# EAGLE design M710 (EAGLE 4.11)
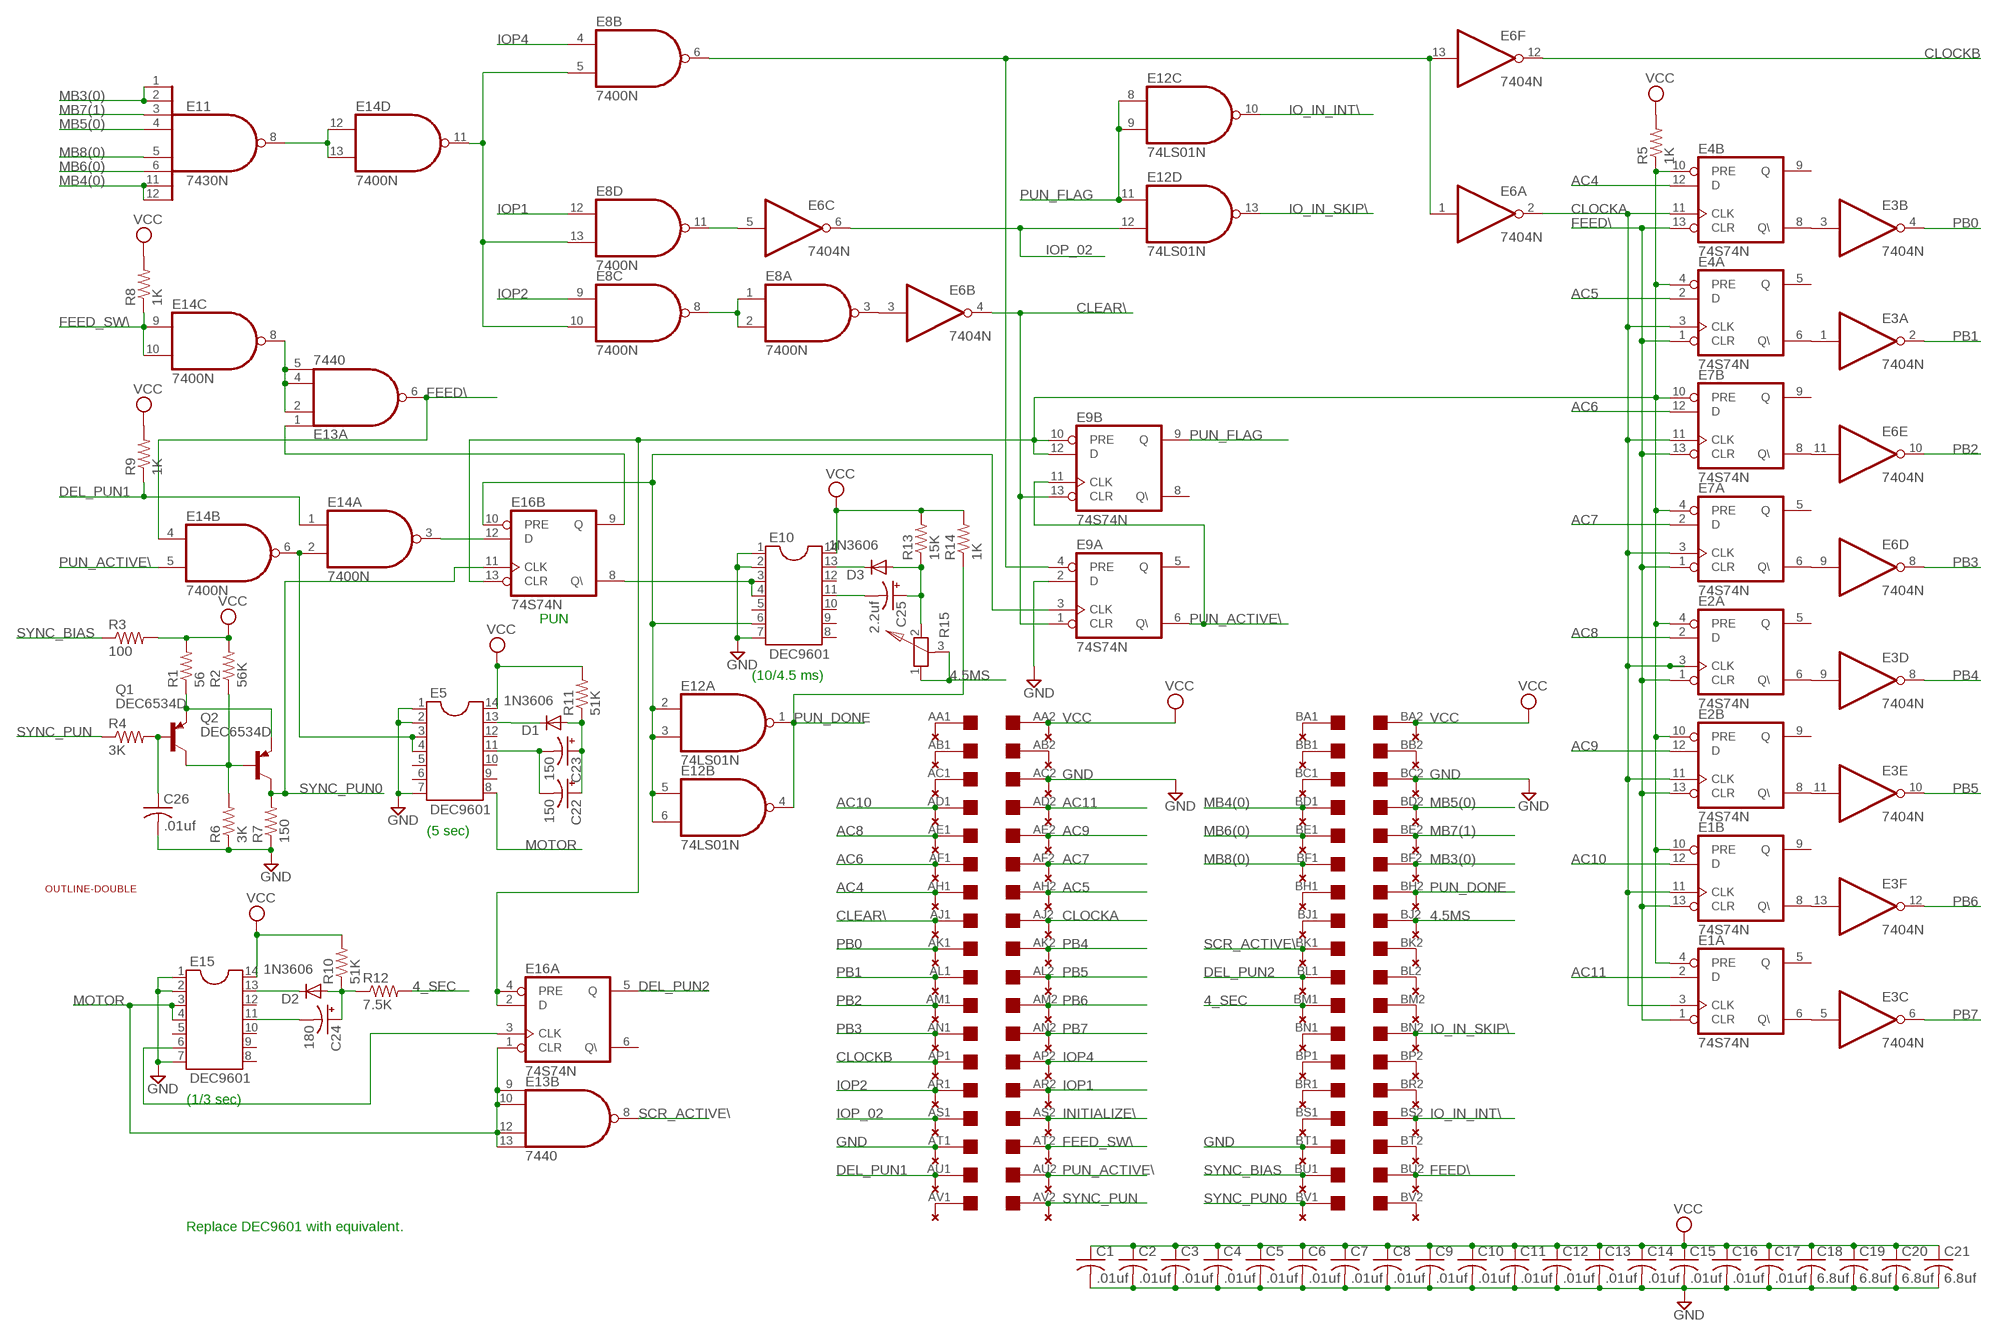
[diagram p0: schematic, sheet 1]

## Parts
C1  .01uf  C-US050-025X075  [C050-025X075]
C2  .01uf  C-US050-025X075  [C050-025X075]
C3  .01uf  C-US050-025X075  [C050-025X075]
C4  .01uf  C-US050-025X075  [C050-025X075]
C5  .01uf  C-US050-025X075  [C050-025X075]
C6  .01uf  C-US050-025X075  [C050-025X075]
C7  .01uf  C-US050-025X075  [C050-025X075]
C8  .01uf  C-US050-025X075  [C050-025X075]
C9  .01uf  C-US050-025X075  [C050-025X075]
C10  .01uf  C-US050-025X075  [C050-025X075]
C11  .01uf  C-US050-025X075  [C050-025X075]
C12  .01uf  C-US050-025X075  [C050-025X075]
C13  .01uf  C-US050-025X075  [C050-025X075]
C14  .01uf  C-US050-025X075  [C050-025X075]
C15  .01uf  C-US050-025X075  [C050-025X075]
C16  .01uf  C-US050-025X075  [C050-025X075]
C17  .01uf  C-US050-025X075  [C050-025X075]
C18  6.8uf  C-US150-054X183  [C150-054X183]
C19  6.8uf  C-US150-054X183  [C150-054X183]
C20  6.8uf  C-US150-054X183  [C150-054X183]
C21  6.8uf  C-US150-054X183  [C150-054X183]
C22  150  CPOL-USE5-8.5  [E5-8,5]
C23  150  CPOL-USE5-8.5  [E5-8,5]
C24  180  CPOL-USE5-8.5  [E5-8,5]
C25  2.2uf  CPOL-USE5-8.5  [E5-8,5]
C26  .01uf  C-US050-025X075  [C050-025X075]
D1  1N3606  1N4004  [DO41-10]
D2  1N3606  1N4004  [DO41-10]
D3  1N3606  1N4004  [DO41-10]
E1  74S74N  [DIL14]
E2  74S74N  [DIL14]
E3  7404N  [DIL14]
E4  74S74N  [DIL14]
E5  DEC9601  DIL14  [DIL14]
E6  7404N  [DIL14]
E7  74S74N  [DIL14]
E8  7400N  [DIL14]
E9  74S74N  [DIL14]
E10  DEC9601  DIL14  [DIL14]
E11  7430N  [DIL14]
E12  74LS01N  [DIL14]
E13  7440  74S20N  [DIL14]
E14  7400N  [DIL14]
E15  DEC9601  DIL14  [DIL14]
E16  74S74N  [DIL14]
Q1  DEC6534D  2N3906  [TO92]
Q2  DEC6534D  2N3906  [TO92]
R1  56  R-US_0207/7  [0207/7]
R2  56K  R-US_0207/7  [0207/7]
R3  100  R-US_0207/7  [0207/7]
R4  3K  R-US_0207/7  [0207/7]
R5  1K  R-US_0207/7  [0207/7]
R6  3K  R-US_0207/7  [0207/7]
R7  150  R-US_0207/7  [0207/7]
R8  1K  R-US_0207/7  [0207/7]
R9  1K  R-US_0207/7  [0207/7]
R10  51K  R-US_0207/7  [0207/7]
R11  51K  R-US_0207/7  [0207/7]
R12  7.5K  R-US_0207/7  [0207/7]
R13  15K  R-US_0207/7  [0207/7]
R14  1K  R-US_0207/7  [0207/7]
R15  POT-TRIM  [PT-SPIN]
U$1  OUTLINE-DOUBLE  [DOUBLE]
U$2  DOUBLE  [EDGE-CON4]
U$5  THRU-HOLE2  [THRU-HOLEB]
U$7  THRU-HOLE2  [THRU-HOLEB]

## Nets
4.5MS: R15.1 R15.3 U$2.BJ2 U$5.J2
4_SEC: R12.2 U$2.BM1 U$5.M1
AC4: E4.12(B:D) U$2.AH1 U$7.H1
AC5: E4.2(A:D) U$2.AH2 U$7.H2
AC6: E7.12(B:D) U$2.AF1 U$7.F1
AC7: E7.2(A:D) U$2.AF2 U$7.F2
AC8: E2.2(A:D) U$2.AE1 U$7.E1
AC9: E2.12(B:D) U$2.AE2 U$7.E2
AC10: E1.12(B:D) U$2.AD1 U$7.D1
AC11: E1.2(A:D) U$2.AD2 U$7.D2
CLEAR\: E6.4(B:O) E9.1(A:CLR) E9.13(B:CLR) U$2.AJ1 U$7.J1
CLOCKA: E1.3(A:CLK) E1.11(B:CLK) E2.3(A:CLK) E2.11(B:CLK) E4.3(A:CLK) E4.11(B:CLK) E6.2(A:O) E7.3(A:CLK) E7.11(B:CLK) U$2.AJ2 U$7.J2
CLOCKB: E6.12(F:O) U$2.AP1 U$7.P1
DEL_PUN1: E14.1(A:I0) R9.1 U$2.AU1 U$7.U1
DEL_PUN2: E16.5(A:Q) U$2.BL1 U$5.L1
FEED\: E1.1(A:CLR) E1.13(B:CLR) E2.1(A:CLR) E2.13(B:CLR) E4.1(A:CLR) E4.13(B:CLR) E7.1(A:CLR) E7.13(B:CLR) E13.6(A:O) E14.4(B:I0) U$2.BU2 U$5.U2
FEED_SW\: E14.9(C:I0) E14.10(C:I1) R8.1 U$2.AT2 U$7.T2
GND: C1.2 C2.2 C3.2 C4.2 C5.2 C6.2 C7.2 C8.2 C9.2 C10.2 C11.2 C12.2 C13.2 C14.2 C15.2 C16.2 C17.2 C18.2 C19.2 C20.2 C21.2 C26.2 E5.1 E5.2 E5.7 E9.2(A:D) E10.1 E10.2 E10.7 E15.1 E15.2 E15.7 R6.1 R7.1 U$2.AC2 U$2.AT1 U$2.BC2 U$2.BT1 U$5.C2 U$5.T1 U$7.C2 U$7.T1
INITIALIZE\: U$2.AS2 U$7.S2
IO_IN_INT\: E12.10(C:O) U$2.BS2 U$5.S2
IO_IN_SKIP\: E12.13(D:O) U$2.BN2 U$5.N2
IOP1: E8.12(D:I0) U$2.AR2 U$7.R2
IOP2: E8.9(C:I0) U$2.AR1 U$7.R1
IOP4: E8.4(B:I0) U$2.AP2 U$7.P2
IOP_02: E6.6(C:O) E12.12(D:I1) U$2.AS1 U$7.S1
MB3(0): E11.1(I0) E11.2(I1) U$2.BF2 U$5.F2
MB4(0): E11.11(I6) E11.12(I7) U$2.BD1 U$5.D1
MB5(0): E11.4(I3) U$2.BD2 U$5.D2
MB6(0): E11.6(I5) U$2.BE1 U$5.E1
MB7(1): E11.3(I2) U$2.BE2 U$5.E2
MB8(0): E11.5(I4) U$2.BF1 U$5.F1
MOTOR: E5.8 E13.9(B:I0) E13.10(B:I1) E13.12(B:I2) E13.13(B:I3) E15.3 E15.4 E16.1(A:CLR)
N$1: U$2.AB2 U$7.B2
N$2: E3.3(B:I) E4.8(B:Q\)
N$3: E3.1(A:I) E4.6(A:Q\)
N$4: E6.1(A:I) E6.13(F:I) E8.6(B:O) E9.4(A:PRE)
N$5: E11.8(O) E14.12(D:I0) E14.13(D:I1)
N$6: E6.3(B:I) E8.3(A:O)
N$7: E8.1(A:I0) E8.2(A:I1) E8.8(C:O)
N$8: E8.5(B:I1) E8.10(C:I1) E8.13(D:I1) E14.11(D:O)
N$9: E2.6(A:Q\) E3.9(D:I)
N$10: E2.8(B:Q\) E3.11(E:I)
N$11: E1.8(B:Q\) E3.13(F:I)
N$12: E1.6(A:Q\) E3.5(C:I)
N$13: E6.11(E:I) E7.8(B:Q\)
N$14: E6.9(D:I) E7.6(A:Q\)
N$15: U$2.AV1 U$7.V1
N$16: E6.5(C:I) E8.11(D:O)
N$17: U$2.AC1 U$7.C1
N$18: U$2.AB1 U$7.B1
N$19: Q1.1(C) Q2.2(B) R2.1 R6.2
N$20: U$2.BS1 U$5.S1
N$21: U$2.BR1 U$5.R1
N$22: U$2.BP1 U$5.P1
N$23: U$2.BN1 U$5.N1
N$26: U$2.AA1 U$7.A1
N$27: U$2.BJ1 U$5.J1
N$28: U$2.BH1 U$5.H1
N$29: U$2.BC1 U$5.C1
N$30: U$2.BB1 U$5.B1
N$31: U$2.BA1 U$5.A1
N$32: U$2.BV2 U$5.V2
N$33: U$2.BT2 U$5.T2
N$34: U$2.BR2 U$5.R2
N$35: U$2.BP2 U$5.P2
N$36: Q1.3(E) Q2.3(E) R1.1
N$37: U$2.BM2 U$5.M2
N$38: C26.1 Q1.2(B) R4.2
N$39: U$2.BL2 U$5.L2
N$40: C24.- E15.11
N$41: E13.2(A:I1) E13.4(A:I2) E13.5(A:I3) E14.8(C:O)
N$42: U$2.BK2 U$5.K2
N$43: U$2.BB2 U$5.B2
N$47: E1.4(A:PRE) E1.10(B:PRE) E2.4(A:PRE) E2.10(B:PRE) E4.4(A:PRE) E4.10(B:PRE) E7.4(A:PRE) E7.10(B:PRE) E9.10(B:PRE) E9.12(B:D) E16.2(A:D) E16.4(A:PRE) E16.13(B:CLR) R5.1
N$49: C25.- E10.11
N$53: E13.1(A:I0) E16.9(B:Q)
N$54: E14.3(A:O) E16.12(B:D)
N$55: E5.3 E5.4 E14.2(A:I1) E14.6(B:O)
N$56: C22.- C23.- E5.11
N$57: D1.C E5.13
N$58: C22.+ C23.+ D1.A R11.1
N$59: D2.C E15.13
N$60: C24.+ D2.A R10.1 R12.1
N$61: E15.6 E16.3(A:CLK)
N$63: D3.C E10.13
N$64: C25.+ D3.A R13.1 R15.2
N$65: E10.3 E10.4 E16.8(B:Q\)
N$66: E9.3(A:CLK) E10.6 E12.2(A:I0) E12.3(A:I1) E12.5(B:I0) E12.6(B:I1) E16.10(B:PRE)
PB0: E3.4(B:O) U$2.AK1 U$7.K1
PB1: E3.2(A:O) U$2.AL1 U$7.L1
PB2: E6.10(E:O) U$2.AM1 U$7.M1
PB3: E6.8(D:O) U$2.AN1 U$7.N1
PB4: E3.8(D:O) U$2.AK2 U$7.K2
PB5: E3.10(E:O) U$2.AL2 U$7.L2
PB6: E3.12(F:O) U$2.AM2 U$7.M2
PB7: E3.6(C:O) U$2.AN2 U$7.N2
PUN_ACTIVE\: E9.6(A:Q\) E9.11(B:CLK) E14.5(B:I1) U$2.AU2 U$7.U2
PUN_DONE: E12.1(A:O) E12.4(B:O) R14.1 U$2.BH2 U$5.H2
PUN_FLAG: E9.9(B:Q) E12.8(C:I0) E12.9(C:I1) E12.11(D:I0)
SCR_ACTIVE\: E13.8(B:O) U$2.BK1 U$5.K1
SYNC_BIAS: R3.1 U$2.BU1 U$5.U1
SYNC_PUN: R4.1 U$2.AV2 U$7.V2
SYNC_PUN0: E16.11(B:CLK) Q2.1(C) R7.2 U$2.BV1 U$5.V1
VCC: C1.1 C2.1 C3.1 C4.1 C5.1 C6.1 C7.1 C8.1 C9.1 C10.1 C11.1 C12.1 C13.1 C14.1 C15.1 C16.1 C17.1 C18.1 C19.1 C20.1 C21.1 E5.14 E10.14 E15.14 R1.2 R2.2 R3.2 R5.2 R8.2 R9.2 R10.2 R11.2 R13.2 R14.2 U$2.AA2 U$2.BA2 U$5.A2 U$7.A2
Unconnected: E1.5(A:Q) E1.9(B:Q) E2.5(A:Q) E2.9(B:Q) E4.5(A:Q) E4.9(B:Q) E5.5 E5.6 E5.9 E5.10 E5.12 E7.5(A:Q) E7.9(B:Q) E9.5(A:Q) E9.8(B:Q\) E10.5 E10.8 E10.9 E10.10 E10.12 E15.5 E15.8 E15.9 E15.10 E15.12 E16.6(A:Q\)

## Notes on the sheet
- PUN
- (10/4.5 ms)
- (5 sec)
- (1/3 sec)
- Replace DEC9601 with equivalent.

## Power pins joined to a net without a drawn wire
GND: E1.7(P:GND) E2.7(P:GND) E3.7(P:GND) E4.7(P:GND) E6.7(P:GND) E7.7(P:GND) E8.7(P:GND) E9.7(P:GND) E11.7(GND) E12.7(P:GND) E13.7(P:GND) E14.7(P:GND) E16.7(P:GND)
VCC: E1.14(P:VCC) E2.14(P:VCC) E3.14(P:VCC) E4.14(P:VCC) E6.14(P:VCC) E7.14(P:VCC) E8.14(P:VCC) E9.14(P:VCC) E11.14(VCC) E12.14(P:VCC) E13.14(P:VCC) E14.14(P:VCC) E16.14(P:VCC)

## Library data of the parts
C1-C21 C26 = rcl:C-US: CAPACITOR, American symbol
C22-C25 = rcl:CPOL-US: POLARIZED CAPACITOR, American symbol
D1-D3 = diode:1N4004: DIODE
E1 E2 E4 E7 E9 E16 = 74xx-us:74*74: Dual D type positive edge triggered FLIP FLOP, preset and clear
E3 E6 = 74xx-us:74*04: Hex INVERTER
E5 E10 E15 = ic-package:DIL14: Dual In Line
E8 E14 = 74xx-us:74*00: Quad 2-input NAND gate
E11 = 74xx-us:74*30: 8-input NAND gate
E12 = 74xx-us:74*01: Quad 2-input NAND gate, open collector
E13 = 74xx-us:74*20: Dual 4-input NAND gate
Q1 Q2 = transistor-pnp:2N3906: PNP Transistor
R1-R14 = rcl:R-US_: RESISTOR, American symbol
R15 = discrete:POT-TRIM
U$1 = dec-con:OUTLINE-*: Board outlines for DEC boards.
U$2 = dec-con:DOUBLE: Double-Height DEC board
U$5 U$7 = dec-con:THRU-HOLE2: Thru-Hole addition to double-sided edge connector.

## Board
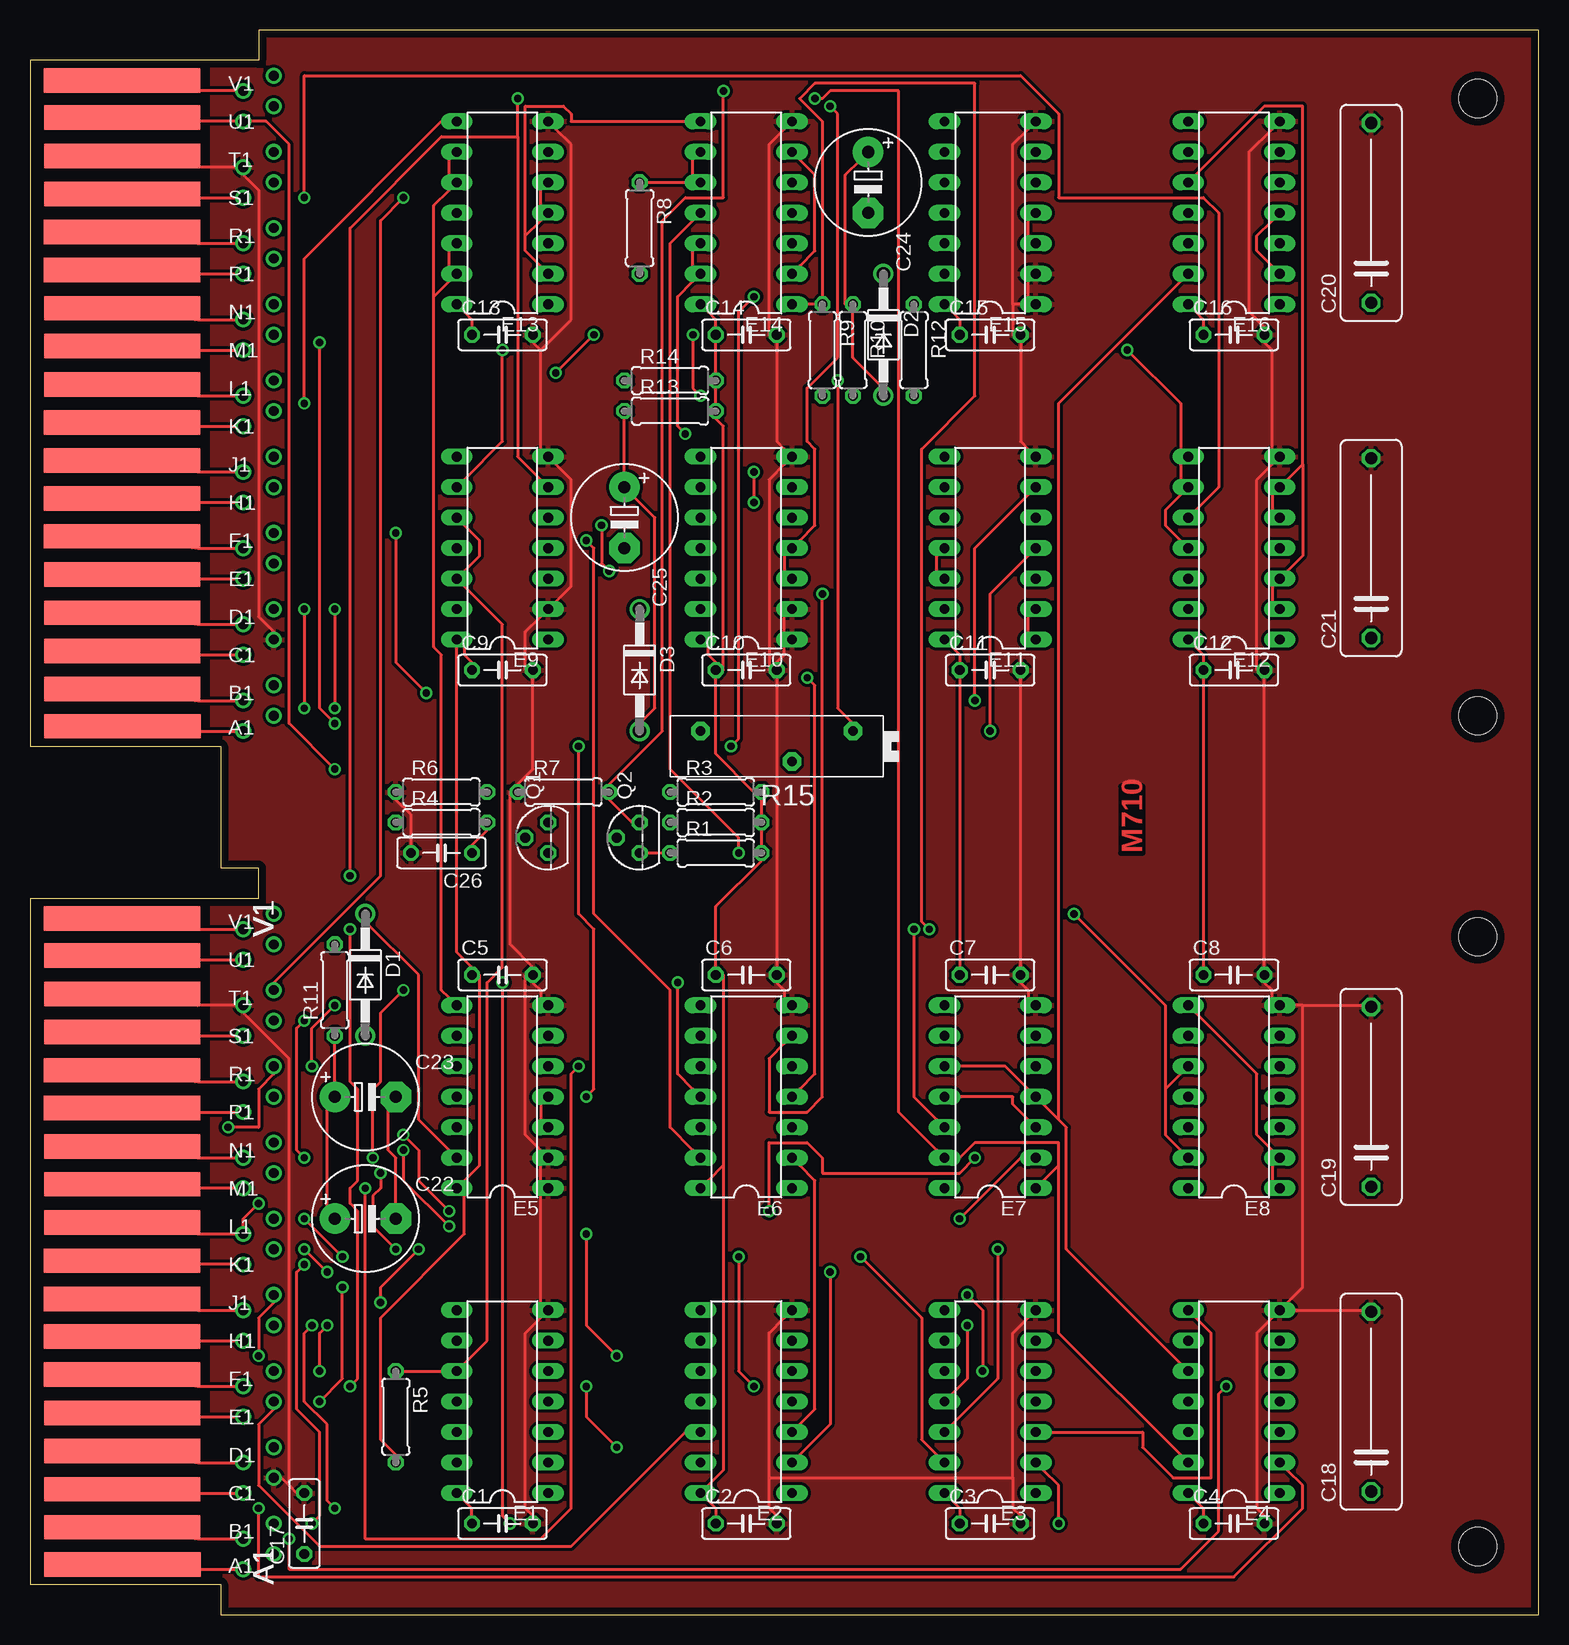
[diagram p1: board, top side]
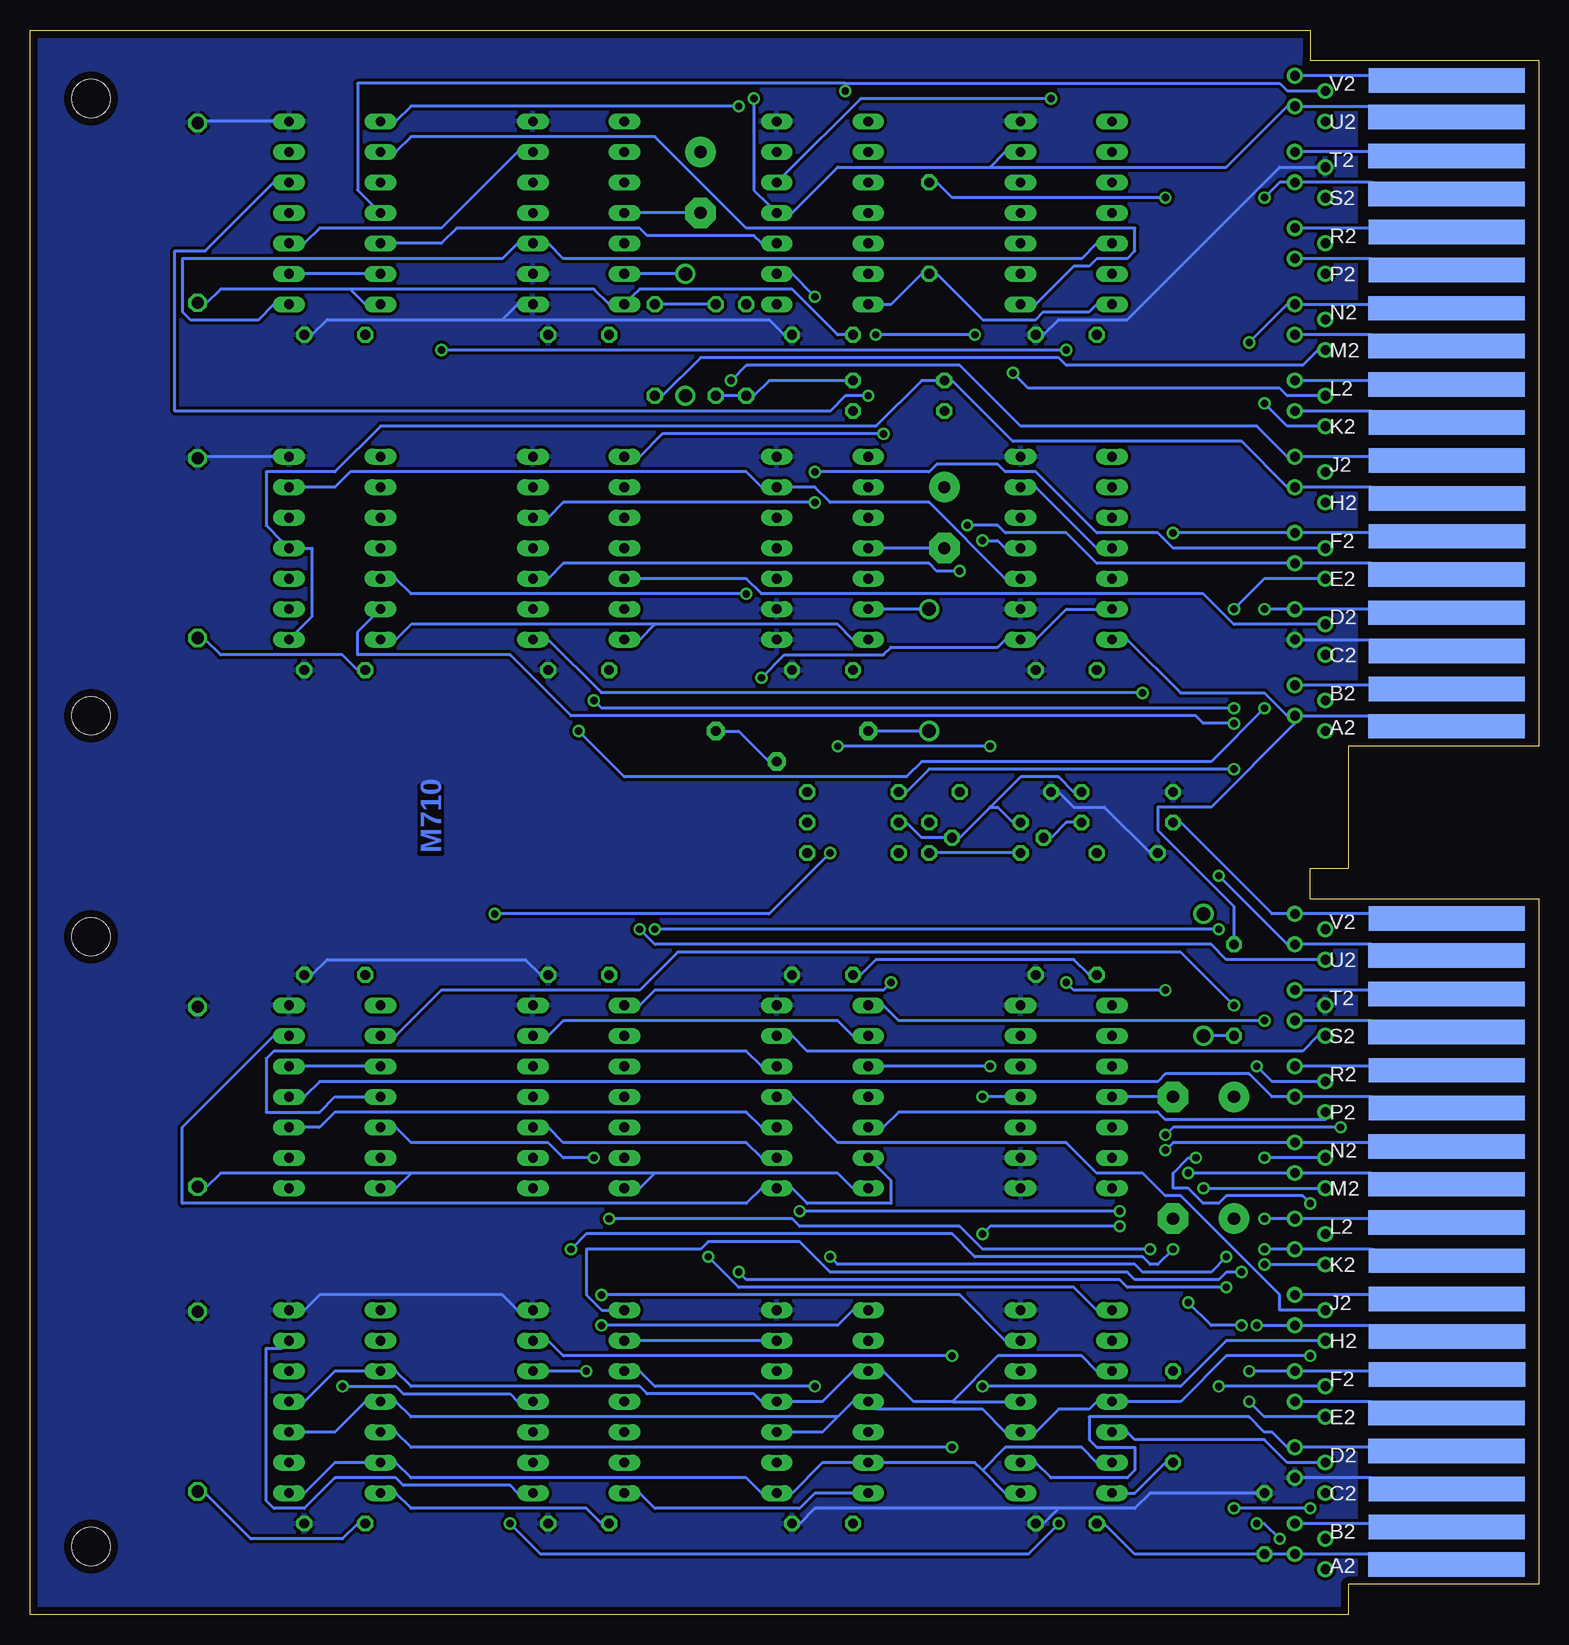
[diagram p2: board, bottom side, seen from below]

Size 125.73 x 132.08 mm. Coordinates in mm from the lower left corner, seen from the top.
Outline: 0,129.03 0,72.39
Copper layers (1*16): Top 0.035mm / dielectric 1.5mm / Bottom 0.035mm
Design rules "olimex10mil": minimum track width 10mil, minimum drill 24mil, track to track 10mil, track to pad 10mil, pad to pad 10mil, via to via 10mil, smd to smd 10mil, copper to edge 25mil, drill to drill 10mil, minimum pad ring 10mil, minimum via ring 8mil, stop-mask expansion 0mil, vias tented up to drill 0mil, thermal gap 10mil
vRestrict: area 31.8,108 to 41.9,125.7; area 49.5,108 to 59.7,125.7; area 67.3,108 to 77.5,125.7; area 85.1,108 to 95.3,125.7; area 102.9,108 to 113,125.7; area 31.8,80 to 41.9,97.8; area 49.5,80 to 59.7,97.8; area 67.3,80 to 77.5,97.8; area 85.1,80 to 95.3,97.8; area 31.8,34.3 to 41.9,52.1; area 49.5,34.3 to 59.7,52.1; area 67.3,34.3 to 77.5,52.1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

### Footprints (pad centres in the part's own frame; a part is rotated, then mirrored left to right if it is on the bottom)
C050-025X075 = drill 0.813 octagon: 1 -2.54,0; 2 2.54,0
C150-054X183 = drill 1.016 octagon: 1 -7.493,0; 2 7.493,0
E5-8,5 = drill 1.016 pad 2.54 round: + -2.54,0 | drill 1.016 pad 2.54 octagon: - 2.54,0
DO41-10 = drill 1.118 round: A 5.08,0; C -5.08,0
DIL14 = drill 0.813 long: 1 -7.62,-3.81; 2 -5.08,-3.81; 3 -2.54,-3.81; 4 0,-3.81; 5 2.54,-3.81; 6 5.08,-3.81; 7 7.62,-3.81; 8 7.62,3.81; 9 5.08,3.81; 10 2.54,3.81; 11 0,3.81; 12 -2.54,3.81; 13 -5.08,3.81; 14 -7.62,3.81
TO92 = drill 0.813 octagon: 1 1.27,0; 2 0,1.905; 3 -1.27,0
0207/7 = drill 0.813 octagon: 1 -3.81,0; 2 3.81,0
PT-SPIN = drill 0.813 pad 1.524 octagon: 1 -6.35,-1.27; 2 6.35,-1.27; 3 -1.27,1.27
DOUBLE = hole 3.175: 120.65,56.515; 120.65,5.715; 120.65,74.93; 120.65,126.365
EDGE-CON4 = smd 13.017 x 2.032: AA1 7.709,4.207; AB1 7.684,7.312; AC1 7.684,10.474; AD1 7.684,13.665; AE1 7.693,16.84; AF1 7.668,20.041; AH1 7.668,23.19; AJ1 7.668,26.34; AK1 7.668,29.515; AL1 7.693,32.69; AM1 7.693,35.89; AN1 7.693,39.04; AP1 7.668,42.24; AR1 7.668,45.39; AS1 7.693,48.565; AT1 7.693,51.74; AU1 7.693,54.94; AV1 7.668,58.026; BA1 7.709,74.057; BB1 7.684,77.162; BC1 7.684,80.324; BD1 7.684,83.515; BE1 7.693,86.69; BF1 7.668,89.891; BH1 7.668,93.04; BJ1 7.668,96.19; BK1 7.668,99.365; BL1 7.693,102.54; BM1 7.693,105.74; BN1 7.693,108.89; BP1 7.668,112.09; BR1 7.668,115.24; BS1 7.693,118.415; BT1 7.693,121.59; BU1 7.693,124.79; BV1 7.668,127.876 | smd 13.017 x 2.032 bottom: AA2 7.69,4.207; AB2 7.668,7.328; AC2 7.668,10.49; AD2 7.693,13.665; AE2 7.693,16.84; AF2 7.642,20.041; AH2 7.642,23.19; AJ2 7.668,26.34; AK2 7.668,29.515; AL2 7.693,32.69; AM2 7.693,35.89; AN2 7.693,39.04; AP2 7.668,42.24; AR2 7.668,45.39; AS2 7.693,48.565; AT2 7.693,51.74; AU2 7.693,54.966; AV2 7.668,58.026; BA2 7.69,74.057; BB2 7.668,77.178; BC2 7.668,80.34; BD2 7.693,83.515; BE2 7.693,86.69; BF2 7.642,89.891; BH2 7.642,93.04; BJ2 7.668,96.19; BK2 7.668,99.365; BL2 7.693,102.54; BM2 7.693,105.74; BN2 7.693,108.89; BP2 7.668,112.09; BR2 7.668,115.24; BS2 7.693,118.415; BT2 7.693,121.59; BU2 7.693,124.816; BV2 7.668,127.876
THRU-HOLEB = drill 0.813 pad 1.27 round: A1 17.78,3.81; A2 20.32,5.08; B1 17.78,6.35; B2 20.32,7.62; C1 17.78,10.16; C2 20.32,11.43; D1 17.78,12.7; D2 20.32,13.97; E1 17.78,16.51; E2 20.32,17.78; F1 17.78,19.05; F2 20.32,20.32; H1 17.78,22.86; H2 20.32,24.13; J1 17.78,25.4; J2 20.32,26.67; K1 17.78,29.21; K2 20.32,30.48; L1 17.78,31.75; L2 20.32,33.02; M1 17.78,35.56; M2 20.32,36.83; N1 17.78,38.1; N2 20.32,39.37; P1 17.78,41.91; P2 20.32,43.18; R1 17.78,44.45; R2 20.32,45.72; S1 17.78,48.26; S2 20.32,49.53; T1 17.78,50.8; T2 20.32,52.07; U1 17.78,54.61; U2 20.32,55.88; V1 17.78,57.15; V2 20.32,58.42

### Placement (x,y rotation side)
C1  39.37,7.62 0 top
C2  59.69,7.62 0 top
C3  80.01,7.62 0 top
C4  100.33,7.62 0 top
C5  39.37,53.34 0 top
C6  59.69,53.34 0 top
C7  80.01,53.34 0 top
C8  100.33,53.34 0 top
C9  39.37,78.74 0 top
C10  59.69,78.74 0 top
C11  80.01,78.74 0 top
C12  100.33,78.74 0 top
C13  39.37,106.68 0 top
C14  59.69,106.68 0 top
C15  80.01,106.68 0 top
C16  100.33,106.68 0 top
C17  22.86,7.62 90 top
C18  111.76,17.78 90 top
C19  111.76,43.18 90 top
C20  111.76,116.84 90 top
C21  111.76,88.9 90 top
C22  27.94,33.02 0 top
C23  27.94,43.18 0 top
C24  69.85,119.38 270 top
C25  49.53,91.44 270 top
C26  34.29,63.5 180 top
D1  27.94,53.34 270 top
D2  71.12,106.68 270 top
D3  50.8,78.74 270 top
E1  39.37,17.78 90 top
E2  59.69,17.78 90 top
E3  80.01,17.78 90 top
E4  100.33,17.78 90 top
E5  39.37,43.18 90 top
E6  59.69,43.18 90 top
E7  80.01,43.18 90 top
E8  100.33,43.18 90 top
E9  39.37,88.9 90 top
E10  59.69,88.9 90 top
E11  80.01,88.9 90 top
E12  100.33,88.9 90 top
E13  39.37,116.84 90 top
E14  59.69,116.84 90 top
E15  80.01,116.84 90 top
E16  100.33,116.84 90 top
Q1  43.18,64.77 90 top
Q2  50.8,64.77 90 top
R1  57.15,63.5 0 top
R2  57.15,66.04 0 top
R3  57.15,68.58 0 top
R4  34.29,66.04 0 top
R5  30.48,16.51 270 top
R6  34.29,68.58 0 top
R7  44.45,68.58 0 top
R8  50.8,115.57 270 top
R9  66.04,105.41 270 top
R10  68.58,105.41 270 top
R11  25.4,52.07 90 top
R12  73.66,105.41 270 top
R13  53.34,100.33 0 top
R14  53.34,102.87 0 top
R15  62.23,72.39 180 top
U$1  0,0 0 top
U$2  0,0 0 top
U$5  0,69.85 0 top
U$7  0,0 0 top

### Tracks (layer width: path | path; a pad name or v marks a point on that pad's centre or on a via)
4.5MS  (via drill 0.61)
  Top 0.254: v67.31,102.87 67.31,75.56 68.58,74.3 R15.1
  Bottom 0.254: R15.3 64.14,71.12 66.68,73.66 67.95,73.66 R15.1 | v67.31,102.87 66.04,104.14 48.26,104.14 43.18,99.06 23.5,99.06 20.96,96.52 U$5.J2 19.69,96.52 13.97,96.52 U$2.BJ2
4_SEC
  Top 0.254: U$5.M1 17.15,105.41 13.97,105.41 U$2.BM1
  Bottom 0.254: R12.2 73.03,101.6 69.85,104.78 40.01,104.78 39.37,104.14 19.69,104.14 18.42,105.41 U$5.M1
AC4  (via drill 0.61)
  Top 0.254: U$7.H1 17.15,22.86 13.97,22.86 U$2.AH1 | v48.9,13.97 46.36,16.51 v46.36,19.05
  Bottom 0.254: v48.9,13.97 93.98,13.97 95.25,15.24 E4.12 | v46.36,19.05 29.85,19.05 26.04,22.86 18.42,22.86 U$7.H1
AC5  (via drill 0.61)
  Top 0.254: v19.05,8.89 19.05,3.17 100.33,3.17 106.05,8.89 106.05,10.79 104.78,12.06 E4.2 | v25.4,8.89 24.77,9.53 24.77,15.88 22.86,17.78 22.86,23.5 v23.5,24.13
  Bottom 0.254: v19.05,8.89 v25.4,8.89 | v23.5,24.13 20.96,24.13 U$7.H2 19.69,24.13 13.97,24.13 U$2.AH2
AC6  (via drill 0.61)
  Top 0.254: U$7.F1 17.15,19.05 13.97,19.05 U$2.AF1 | v73.66,57.15 73.66,43.18 75.57,41.27 E7.12 | v26.67,57.15 26.67,44.45 27.31,43.81 27.31,36.2 26.67,35.56 26.67,34.29 27.31,33.66 27.31,19.68 v26.67,19.05
  Bottom 0.254: v26.67,57.15 v73.66,57.15 | v26.67,19.05 18.42,19.05 U$7.F1
AC7  (via drill 0.61)
  Top 0.254: v77.47,33.02 82.55,38.1 E7.2 | v32.39,30.48 29.21,27.3 v29.21,26.04 | v24.77,24.13 24.13,23.5 v24.13,20.32
  Bottom 0.254: v77.47,33.02 62.23,33.02 61.6,32.38 48.26,32.38 46.36,30.48 v32.39,30.48 | v29.21,26.04 27.31,24.13 v24.77,24.13 | v24.13,20.32 20.96,20.32 U$7.F2 19.69,20.32 13.97,20.32 U$2.AF2
AC8  (via drill 0.61)
  Top 0.254: U$7.E1 17.15,16.51 13.97,16.51 U$2.AE1 | v66.68,28.57 66.68,15.88 64.14,13.34 E2.2 | v26.04,27.3 26.04,19.68 v24.13,17.78
  Bottom 0.254: v66.68,28.57 66.04,27.94 34.93,27.94 34.29,27.3 v26.04,27.3 | v24.13,17.78 22.86,16.51 18.42,16.51 U$7.E1
AC9
  Top 0.254: E2.12 54.61,15.24 45.09,5.71 24.13,5.71 19.05,10.79 19.05,15.88 20.32,17.14 U$7.E2
  Bottom 0.254: U$7.E2 19.69,17.78 13.97,17.78 U$2.AE2
AC10
  Top 0.254: U$7.D1 17.15,12.7 13.97,12.7 U$2.AD1
  Bottom 0.254: E1.12 34.29,15.24 33.66,14.61 22.86,14.61 20.96,12.7 18.42,12.7 U$7.D1
AC11
  Bottom 0.254: E1.2 41.91,12.7 40.64,11.43 34.29,11.43 33.66,12.06 33.66,13.97 36.83,13.97 37.47,14.61 37.47,16.51 24.13,16.51 22.86,15.24 22.23,15.24 20.96,13.97 U$7.D2 19.69,13.97 13.97,13.97 U$2.AD2
CLEAR\  (via drill 0.61)
  Top 0.254: U$7.J1 17.15,25.4 13.97,25.4 U$2.AJ1 | v64.77,78.11 65.41,77.47 65.41,45.09 64.14,43.81 E6.4
  Bottom 0.254: E9.13 36.83,83.82 39.37,83.82 41.91,81.28 E9.1 44.45,81.28 45.09,80.64 53.98,80.64 54.61,80.01 62.87,80.01 v64.77,78.11 | E6.4 62.23,43.18 58.42,39.37 39.37,39.37 36.83,36.83 33.02,36.83 31.12,34.92 29.85,34.92 21.59,26.67 21.59,25.4 18.42,25.4 U$7.J1
CLOCKA  (via drill 0.61)
  Top 0.254: E7.11 77.47,43.18 81.92,43.18 81.92,42.55 83.19,41.27 E7.3 | E6.2 64.14,37.47 65.41,36.2 65.41,17.14 64.14,15.88 E2.3 | v19.05,21.59 19.05,24.77 20.32,26.04 U$7.J2
  Bottom 0.254: U$7.J2 19.69,26.67 13.97,26.67 U$2.AJ2 | E6.2 64.77,38.1 66.04,39.37 81.28,39.37 82.55,40.64 E7.3 | E4.3 102.87,15.24 100.33,15.24 97.79,17.78 E4.11 95.25,17.78 93.98,16.51 58.42,16.51 | 58.42,16.51 59.69,15.24 62.23,15.24 E2.3 | 58.42,16.51 57.15,17.78 E2.11 55.25,17.14 46.36,17.14 44.45,15.24 E1.3 41.91,15.24 40.01,17.14 37.47,17.14 36.83,17.78 E1.11 34.29,17.78 29.85,17.78 26.04,21.59 v19.05,21.59
CLOCKB
  Top 0.254: U$7.P1 17.15,41.91 13.97,41.91 U$2.AP1
  Bottom 0.254: E6.12 54.61,40.64 53.34,41.91 31.75,41.91 31.12,41.27 17.78,41.27 U$7.P1
DEL_PUN1  (via drill 0.61)
  Top 0.254: E14.1 64.77,109.22 65.41,109.22 R9.1 66.04,109.86 66.04,124.46 64.14,126.36 65.41,127.64 78.74,127.64 78.74,101.6 74.3,97.16 74.3,57.78 v74.93,57.15 | U$7.U1 17.15,54.61 13.97,54.61 U$2.AU1
  Bottom 0.254: v74.93,57.15 73.66,55.88 27.31,55.88 26.04,54.61 18.42,54.61 U$7.U1
DEL_PUN2  (via drill 0.61)
  Top 0.254: U$5.L1 17.15,101.6 13.97,101.6 U$2.BL1 | v55.88,101.6 55.25,102.23 v55.25,106.68 | v43.82,103.5 v46.99,106.68
  Bottom 0.254: v55.88,101.6 57.79,101.6 59.06,100.33 113.67,100.33 113.67,113.67 111.13,113.67 105.41,119.38 E16.5 | v46.99,106.68 v55.25,106.68 | v43.82,103.5 42.55,102.23 21.59,102.23 20.96,101.6 18.42,101.6 U$5.L1
FEED\  (via drill 0.61)
  Top 0.254: 85.73,37.47 85.73,39.37 78.74,39.37 77.47,38.1 E7.13 75.57,38.73 72.39,41.91 72.39,127 66.68,127 66.04,126.36 v65.41,126.36 | 85.73,37.47 84.46,36.2 E7.1 | 85.73,37.47 85.73,23.5 95.89,13.34 E4.13
  Bottom 0.254: 45.72,120.65 44.45,121.92 E13.6 | 45.72,120.65 58.42,120.65 62.23,116.84 E14.4 64.14,117.47 65.41,118.75 v65.41,126.36 | 46.36,12.06 46.99,12.7 54.61,12.7 E2.13 57.15,12.7 59.69,12.7 62.23,10.16 E2.1 64.77,10.16 66.04,11.43 93.98,11.43 95.25,12.7 E4.13 97.79,12.7 100.33,12.7 102.87,10.16 E4.1 | 46.36,12.06 44.45,10.16 E1.1 | 46.36,12.06 44.45,13.97 38.1,13.97 36.83,12.7 E1.13 | U$2.BU2 13.97,125.73 19.69,125.73 U$5.U2 20.96,125.73 26.04,120.65 45.72,120.65
FEED_SW\  (via drill 0.61)
  Top 0.254: R8.1 51.44,119.38 54.61,119.38 E14.10 55.25,120.02 55.25,121.28 E14.9 | v31.12,118.11 29.21,116.2 29.21,61.59 20.32,52.7 U$7.T2
  Bottom 0.254: U$7.T2 19.69,52.07 13.97,52.07 U$2.AT2 | v31.12,118.11 48.9,118.11 50.17,119.38 R8.1
GND
  Top 0.254: E14.7 62.87,123.83 61.6,122.56 61.6,106.68 C14.2 62.23,106.05 62.23,97.79 62.87,97.16 E10.7 62.87,95.89 61.6,94.61 61.6,78.74 C10.2 | E6.7 62.87,51.44 62.87,52.07 62.23,52.7 C6.2 62.23,53.98 62.23,78.11 C10.2 | C10.2 62.23,79.38 62.87,80.01 62.87,80.64 E10.1 62.87,81.92 62.87,83.19 E10.2 | E15.2 83.19,111.12 83.19,109.86 E15.1 82.55,109.22 81.92,109.22 | E11.7 83.19,97.16 82.55,97.79 82.55,106.05 C15.2 81.92,106.68 81.92,109.22 | 81.92,109.22 81.92,122.56 83.19,123.83 E15.7 | E16.7 103.51,123.83 101.6,121.92 101.6,108.58 102.87,107.31 C16.2 102.87,106.05 103.51,105.41 103.51,97.16 E12.7 103.51,95.89 102.24,94.61 102.24,78.74 C12.2 102.87,78.11 102.87,53.98 C8.2 102.87,52.7 103.51,52.07 103.51,51.44 E8.7 105.41,50.8 106.05,50.8 | 61.6,11.43 61.6,23.5 62.87,24.77 E2.7 | 61.6,11.43 61.6,8.89 62.23,8.26 C2.2 | 81.92,11.43 81.92,23.5 83.19,24.77 E3.7 | 81.92,11.43 81.92,8.89 82.55,8.26 C3.2 | 61.6,11.43 81.92,11.43 | E7.7 83.19,51.44 83.19,52.07 82.55,52.7 C7.2 82.55,53.98 82.55,78.11 C11.2 | C4.2 102.87,8.26 102.24,8.89 102.24,23.5 103.51,24.77 E4.7 | C18.2 111.13,25.4 105.41,25.4 E4.7 | 106.05,50.8 111.13,50.8 C19.2 | 106.05,50.8 106.05,27.3 104.78,26.04 E4.7 | 21.59,10.79 20.96,11.43 U$7.C2 | 21.59,10.79 22.23,10.16 C17.2 | 21.59,10.79 21.59,46.35 17.78,50.16 U$7.T1 17.15,50.8 13.97,50.8 U$2.AT1 | C1.2 41.91,8.26 41.28,8.89 41.28,23.5 42.55,24.77 E1.7 42.55,26.04 42.55,34.92 E5.1 42.55,36.2 42.55,37.47 E5.2 42.55,38.73 41.28,40.01 41.28,53.34 C5.2 | 42.55,105.41 41.91,106.05 C13.2 | 42.55,105.41 42.55,97.16 E9.7 43.82,95.89 45.09,94.61 45.09,85.72 43.82,84.45 E9.2 42.55,83.19 41.28,81.92 41.28,78.74 C9.2 41.91,78.11 41.91,70.48 40.64,69.22 R7.1 40.01,68.58 40.01,55.88 41.91,53.98 C5.2
  Top 0.254: 42.55,105.41 45.09,107.95 45.09,122.56 43.82,123.83 E13.7 | C26.2 31.75,64.14 31.75,66.67 30.48,67.94 R6.1 | C5.2 41.91,52.7 42.55,52.07 42.55,51.44 E5.7 | U$5.C2 20.32,81.92 19.05,83.19 19.05,118.75 17.78,120.02 U$5.T1 17.15,120.65 13.97,120.65 U$2.BT1
  Bottom 0.254: E16.7 105.41,124.46 111.13,124.46 C20.2 | E12.7 105.41,96.52 111.13,96.52 C21.2 | 86.36,107.95 85.09,109.22 E15.1 | 86.36,107.95 100.97,107.95 102.24,106.68 C16.2 | C7.2 83.19,53.34 84.46,54.61 100.97,54.61 102.24,53.34 C8.2 | E3.7 85.09,25.4 86.36,26.67 101.6,26.67 102.87,25.4 E4.7 | 86.36,107.95 64.14,107.95 62.87,106.68 C14.2 | U$7.C2 19.69,11.43 13.97,11.43 U$2.AC2 | U$5.C2 19.69,81.28 13.97,81.28 U$2.BC2 | C26.2 32.39,63.5 36.2,67.31 38.74,67.31 40.01,68.58 R7.1 | U$5.T1 18.42,120.65 21.59,120.65 34.29,107.95 40.01,107.95 41.28,106.68 C13.2 | 40.01,8.89 33.66,8.89 32.39,10.16 23.5,10.16 C17.2 | 40.01,8.89 41.28,7.62 C1.2 | 40.01,8.89 60.33,8.89 61.6,7.62 C2.2
  pour Bottom (isolate 0.254): 125.73,132.08 125.73,0 15.24,0 15.24,132.08
  pour Top (isolate 0.254): 15.24,132.08 125.73,132.08 125.73,0 15.24,0
INITIALIZE\
  Bottom 0.254: U$7.S2 19.69,49.53 13.97,49.53 U$2.AS2
IO_IN_INT\  (via drill 0.61)
  Top 0.254: v22.86,118.11 22.86,128.27 82.55,128.27 85.73,125.09 85.73,118.11 97.79,118.11 99.06,116.84 99.06,93.98 97.16,92.08 E12.10
  Bottom 0.254: U$2.BS2 13.97,119.38 19.69,119.38 U$5.S2 20.96,119.38 21.59,119.38 v22.86,118.11
IO_IN_SKIP\  (via drill 0.61)
  Top 0.254: v25.4,74.3 24.13,75.56 v24.13,106.05
  Bottom 0.254: v25.4,74.3 27.94,74.3 28.58,74.93 80.65,74.93 85.73,80.01 98.43,80.01 98.43,81.92 97.16,83.19 E12.13 | v24.13,106.05 20.96,109.22 U$5.N2 19.69,109.22 13.97,109.22 U$2.BN2
IOP1  (via drill 0.61)
  Top 0.254: v78.74,38.1 77.47,36.83 66.04,36.83 66.04,38.1 64.77,39.37 61.6,39.37 v61.6,33.66 | v34.93,33.66 32.39,36.2 32.39,38.73 v31.12,40.01 | v16.51,40.64 19.05,40.64 19.05,43.81 20.32,45.09 U$7.R2
  Bottom 0.254: U$7.R2 19.69,45.72 13.97,45.72 U$2.AR2 | v78.74,38.1 81.28,38.1 82.55,39.37 93.98,39.37 95.25,40.64 E8.12 | v34.93,33.66 v61.6,33.66 | v31.12,40.01 30.48,40.64 v16.51,40.64
IOP2  (via drill 0.61)
  Top 0.254: U$7.R1 17.15,44.45 13.97,44.45 U$2.AR1 | v25.4,50.8 23.5,48.9 v23.5,45.72
  Bottom 0.254: v25.4,50.8 29.85,55.24 71.76,55.24 74.93,52.07 91.44,52.07 95.25,48.26 E8.9 | v23.5,45.72 22.23,44.45 18.42,44.45 U$7.R1
IOP4
  Bottom 0.254: E8.4 102.87,43.18 101.6,44.45 31.75,44.45 31.12,45.09 24.13,45.09 22.23,43.18 20.96,43.18 U$7.P2 19.69,43.18 13.97,43.18 U$2.AP2
IOP_02  (via drill 0.61)
  Top 0.254: U$7.S1 17.15,48.26 13.97,48.26 U$2.AS1 | v66.04,85.09 66.04,43.18 64.77,41.91 61.6,41.91 61.6,46.35 62.87,47.62 E6.6
  Bottom 0.254: E6.6 62.23,48.26 60.96,46.99 19.69,46.99 18.42,48.26 U$7.S1 | v66.04,85.09 93.98,85.09 95.25,86.36 E12.12
MB3(0)  (via drill 0.61)
  Top 0.254: E11.1 83.19,81.92 83.19,83.19 E11.2 | v33.02,76.83 30.48,79.38 v30.48,90.17
  Bottom 0.254: v33.02,76.83 78.11,76.83 82.55,81.28 E11.1 | v30.48,90.17 20.96,90.17 U$5.F2 19.69,90.17 13.97,90.17 U$2.BF2
MB4(0)
  Top 0.254: E11.12 75.57,87 75.57,88.27 E11.11 | U$5.D1 17.15,82.55 13.97,82.55 U$2.BD1
  Bottom 0.254: E11.12 74.93,86.36 66.04,86.36 64.77,85.09 27.94,85.09 25.4,82.55 18.42,82.55 U$5.D1
MB5(0)  (via drill 0.61)
  Top 0.254: v80.01,73.66 80.01,85.09 83.19,88.27 E11.4 | v22.86,83.82 v22.86,75.56
  Bottom 0.254: v80.01,73.66 76.2,69.85 52.71,69.85 51.44,71.12 27.31,71.12 v22.86,75.56 | v22.86,83.82 20.96,83.82 U$5.D2 19.69,83.82 13.97,83.82 U$2.BD2
MB6(0)  (via drill 0.61)
  Top 0.254: U$5.E1 17.15,86.36 13.97,86.36 U$2.BE1 | v78.74,76.2 78.74,88.9 83.19,93.34 E11.6 | v25.4,83.82 v25.4,75.56
  Bottom 0.254: v78.74,76.2 78.11,75.56 v25.4,75.56 | v25.4,83.82 22.86,86.36 18.42,86.36 U$5.E1
MB7(1)  (via drill 0.61)
  Top 0.254: v48.26,87 47.63,87.63 v47.63,90.81
  Bottom 0.254: v48.26,87 50.17,87 50.8,87.63 81.28,87.63 82.55,86.36 E11.3 | v47.63,90.81 45.09,90.81 44.45,90.17 39.37,90.17 36.83,87.63 20.96,87.63 U$5.E2 19.69,87.63 13.97,87.63 U$2.BE2
MB8(0)  (via drill 0.61)
  Top 0.254: U$5.F1 17.15,88.9 13.97,88.9 U$2.BF1 | v60.33,95.25 v60.33,92.71
  Bottom 0.254: v60.33,92.71 81.28,92.71 82.55,91.44 E11.5 | v60.33,95.25 50.8,95.25 50.17,95.89 45.09,95.89 44.45,95.25 41.91,95.25 36.83,90.17 31.75,90.17 30.48,88.9 18.42,88.9 U$5.F1
MOTOR
  Top 0.254: E15.3 83.19,114.94 83.19,116.2 E15.4 | E13.9 34.93,121.28 34.93,120.02 E13.10 34.93,118.75 33.66,117.47 33.66,109.86 | 33.66,109.86 33.66,80.64 34.29,80.01 34.29,52.07 34.93,51.44 E5.8 | 33.66,109.86 34.93,111.12 E13.13 34.93,112.39 34.93,113.67 E13.12
  Bottom 0.254: E16.1 105.41,109.22 106.68,107.95 112.4,107.95 113.03,108.58 113.03,113.03 86.36,113.03 85.09,114.3 E15.3 82.55,114.3 81.28,113.03 38.1,113.03 36.83,114.3 E13.12
N$1
  Bottom 0.254: U$7.B2 19.69,7.62 13.97,7.62 U$2.AB2
N$2
  Top 0.254: E3.3 85.09,15.24 92.71,15.24 92.71,13.97 95.25,11.43 98.43,11.43 98.43,23.5 97.16,24.77 E4.8
N$3
  Bottom 0.254: E3.1 85.09,10.16 85.73,10.79 94.62,10.79 95.25,11.43 100.33,11.43 102.87,8.89 105.41,8.89 106.05,9.53 106.05,22.23 104.78,22.23 E4.6
N$4  (via drill 0.61)
  Top 0.254: v46.36,89.53 46.99,88.9 46.99,58.42 53.34,52.07 53.34,40.64 55.25,38.73 E6.13
  Bottom 0.254: E6.13 55.25,37.47 53.98,36.2 53.98,34.29 60.96,34.29 62.23,35.56 E6.1 64.77,35.56 66.04,34.29 113.03,34.29 113.03,40.64 105.41,48.26 E8.6 | v46.36,89.53 45.09,89.53 44.45,88.9 E9.4
N$5  (via drill 0.61)
  Top 0.254: E14.12 55.25,113.67 55.25,112.39 E14.13 55.25,111.12 53.98,109.86 53.98,99.06 v54.61,98.42
  Bottom 0.254: v54.61,98.42 73.03,98.42 74.93,96.52 E11.8
N$6
  Bottom 0.254: E6.3 64.77,40.64 66.04,41.91 100.33,41.91 101.6,40.64 102.87,40.64 E8.3
N$7
  Top 0.254: E8.1 103.51,36.2 103.51,37.47 E8.2 103.51,38.73 102.24,40.01 102.24,45.09 97.16,50.16 E8.8
N$8  (via drill 0.61)
  Top 0.254: 94.62,43.81 94.62,40.01 95.89,38.73 E8.13 | 94.62,43.81 95.89,45.09 E8.10 | v59.06,63.5 59.06,64.77 53.34,70.48 53.34,114.3 55.25,116.2 E14.11 | v87,58.42 94.62,50.8 94.62,43.81
  Bottom 0.254: E8.5 102.87,45.72 97.79,45.72 E8.10 | v59.06,63.5 64.14,58.42 v87,58.42
N$9
  Bottom 0.254: E2.6 64.77,22.86 74.93,22.86 E3.9
N$10  (via drill 0.61)
  Top 0.254: v78.11,24.13 78.11,19.68 76.84,18.41 E3.11
  Bottom 0.254: v78.11,24.13 58.42,24.13 57.15,25.4 E2.8
N$11  (via drill 0.61)
  Top 0.254: v69.22,29.84 74.3,24.77 74.3,14.61 75.57,13.34 E3.13
  Bottom 0.254: v69.22,29.84 66.68,27.3 38.74,27.3 36.83,25.4 E1.8
N$12  (via drill 0.61)
  Top 0.254: v78.11,26.67 79.38,25.4 v79.38,20.32
  Bottom 0.254: v78.11,26.67 48.26,26.67 44.45,22.86 E1.6 | v79.38,20.32 82.55,20.32 E3.5
N$13  (via drill 0.61)
  Top 0.254: v53.98,52.7 53.98,45.09 55.25,43.81 E6.11
  Bottom 0.254: v53.98,52.7 54.61,52.07 73.66,52.07 74.93,50.8 E7.8
N$14
  Bottom 0.254: E6.9 57.15,48.26 58.42,49.53 81.28,49.53 82.55,48.26 E7.6
N$15
  Top 0.254: U$7.V1 17.15,57.15 13.97,57.15 U$2.AV1
N$16
  Bottom 0.254: E6.5 64.77,45.72 66.04,46.99 105.41,46.99 106.05,46.35 106.05,41.91 101.6,41.91 100.33,43.18 97.79,43.18 E8.11
N$17
  Top 0.254: U$7.C1 17.15,10.16 13.97,10.16 U$2.AC1
N$18
  Top 0.254: U$7.B1 17.15,6.35 13.97,6.35 U$2.AB1
N$19
  Bottom 0.254: 45.72,67.31 48.26,64.77 Q2.2 49.53,64.77 51.44,64.77 52.71,66.04 R2.1 | 45.72,67.31 43.18,69.85 40.01,69.85 38.74,68.58 R6.2 | 45.72,67.31 45.09,67.31 43.82,66.04 Q1.1
N$20
  Top 0.254: U$5.S1 17.15,118.11 13.97,118.11 U$2.BS1
N$21
  Top 0.254: U$5.R1 17.15,114.3 13.97,114.3 U$2.BR1
N$22
  Top 0.254: U$5.P1 17.15,111.76 13.97,111.76 U$2.BP1
N$23
  Top 0.254: U$5.N1 17.15,107.95 13.97,107.95 U$2.BN1
N$26
  Top 0.254: U$7.A1 17.15,3.81 13.97,3.81 U$2.AA1
N$27
  Top 0.254: U$5.J1 17.15,95.25 13.97,95.25 U$2.BJ1
N$28
  Top 0.254: U$5.H1 17.15,92.71 13.97,92.71 U$2.BH1
N$29
  Top 0.254: U$5.C1 17.15,80.01 13.97,80.01 U$2.BC1
N$30
  Top 0.254: U$5.B1 17.15,76.2 13.97,76.2 U$2.BB1
N$31
  Top 0.254: U$5.A1 17.15,73.66 13.97,73.66 U$2.BA1
N$32
  Bottom 0.254: U$5.V2 19.69,128.27 13.97,128.27 U$2.BV2
N$33
  Bottom 0.254: U$5.T2 19.69,121.92 13.97,121.92 U$2.BT2
N$34
  Bottom 0.254: U$5.R2 19.69,115.57 13.97,115.57 U$2.BR2
N$35
  Bottom 0.254: U$5.P2 19.69,113.03 13.97,113.03 U$2.BP2
N$36
  Top 0.254: R1.1 52.71,63.5 51.44,63.5 Q2.3
  Bottom 0.254: Q1.3 43.82,63.5 50.17,63.5 Q2.3
N$37
  Bottom 0.254: U$5.M2 19.69,106.68 13.97,106.68 U$2.BM2
N$38
  Top 0.254: C26.1 36.83,64.14 38.1,65.41 R4.2
  Bottom 0.254: Q1.2 40.64,64.77 39.37,66.04 38.74,66.04 R4.2
N$39
  Bottom 0.254: U$5.L2 19.69,102.87 13.97,102.87 U$2.BL2
N$40
  Bottom 0.254: E15.11 74.93,116.84 70.49,116.84 C24.-
N$41
  Top 0.254: 41.28,114.94 41.28,113.67 42.55,112.39 E13.2 | 41.28,114.94 42.55,116.2 E13.4 42.55,117.47 42.55,118.75 E13.5 | 41.28,114.94 41.28,125.73 44.45,125.73 45.09,125.09 45.09,124.46 54.61,124.46 E14.8
N$42
  Bottom 0.254: U$5.K2 19.69,100.33 13.97,100.33 U$2.BK2
N$43
  Bottom 0.254: U$5.B2 19.69,77.47 13.97,77.47 U$2.BB2
N$47
  Top 0.254: E9.10 36.2,90.81 37.47,89.53 37.47,88.27 36.2,87 E9.12 36.2,85.72 39.37,82.55 39.37,53.98 38.1,52.7 38.1,22.86 36.2,20.95 E1.10 34.29,20.32 31.12,20.32 R5.1 | E16.4 103.51,116.2 102.24,114.94 102.24,113.67 103.51,112.39 E16.2 | E7.10 77.47,45.72 81.28,45.72 83.19,43.81 E7.4 84.46,42.55 85.73,41.27 | 85.73,41.27 86.36,40.64 86.36,30.48 95.89,20.95 E4.10 | 85.73,41.27 85.73,100.97 95.89,111.12 E16.13
  Bottom 0.254: 48.9,17.78 52.07,17.78 54.61,20.32 E2.10 57.15,20.32 59.69,17.78 62.23,17.78 E2.4 64.77,17.78 65.41,18.41 74.3,18.41 74.93,19.05 93.98,19.05 95.25,20.32 E4.10 97.79,20.32 100.33,20.32 102.87,17.78 E4.4 | 48.9,17.78 44.45,17.78 E1.4 | 48.9,17.78 45.09,21.59 38.1,21.59 36.83,20.32 E1.10 | E16.13 97.79,111.76 102.87,111.76 E16.2
N$49
  Bottom 0.254: E10.11 54.61,88.9 50.17,88.9 C25.-
N$53
  Bottom 0.254: E13.1 41.91,109.22 38.74,112.39 37.47,112.39 36.83,113.03 34.29,113.03 33.66,113.67 33.66,115.57 66.04,115.57 73.66,123.19 93.98,123.19 95.25,121.92 E16.9
N$54
  Bottom 0.254: E14.3 64.77,114.3 65.41,114.94 74.3,114.94 74.93,115.57 90.17,115.57 91.44,114.3 95.25,114.3 E16.12
N$55  (via drill 0.61)
  Top 0.254: E5.3 42.55,41.27 42.55,42.55 E5.4 | E14.2 64.14,112.39 65.41,113.67 65.41,120.02 64.14,121.28 E14.6 | v46.36,43.18 46.99,43.81 46.99,57.15 45.72,58.42 v45.72,72.39 | v58.42,72.39 59.06,73.03 59.06,108.58 v60.33,109.86
  Bottom 0.254: v46.36,43.18 44.45,43.18 E5.4 | v45.72,72.39 v58.42,72.39 | v60.33,109.86 62.23,111.76 E14.2
N$56
  Top 0.254: C22.- 30.48,33.66 30.48,38.1 29.85,38.73 29.85,42.55 C23.-
  Bottom 0.254: E5.11 34.29,43.18 31.12,43.18 C23.-
N$57
  Top 0.254: E5.13 34.93,38.73 32.39,41.27 32.39,53.34 27.94,57.78 D1.C
N$58
  Top 0.254: R11.1 25.4,47.62 25.4,43.81 C23.+ 24.77,42.55 24.77,33.66 C22.+
  Bottom 0.254: R11.1 26.04,48.26 27.31,48.26 D1.A
N$59
  Bottom 0.254: E15.13 74.93,111.76 71.76,111.76 D2.C
N$60
  Top 0.254: D2.A 71.12,102.23 68.58,104.78 68.58,108.58 R10.1 67.95,109.22 67.95,120.02 69.22,121.28 C24.+
  Bottom 0.254: R10.1 69.22,109.22 73.03,109.22 R12.1
N$61
  Bottom 0.254: E15.6 85.09,121.92 91.44,115.57 101.6,115.57 102.87,114.3 E16.3
N$63
  Bottom 0.254: E10.13 54.61,83.82 51.44,83.82 D3.C
N$64
  Top 0.254: R13.1 49.53,99.69 49.53,94.61 C25.+ 50.17,93.34 52.07,91.44 52.07,75.56 50.8,74.3 D3.A
  Bottom 0.254: R15.2 55.25,73.66 51.44,73.66 D3.A
N$65  (via drill 0.61)
  Top 0.254: E10.3 62.87,87 62.87,88.27 E10.4 64.14,89.53 65.41,90.81 65.41,97.16 64.77,97.79 64.77,102.23 67.31,104.78 67.31,125.09 v66.68,125.73
  Bottom 0.254: v66.68,125.73 93.98,125.73 95.25,124.46 E16.8
N$66
  Top 0.254: E12.2 103.51,84.45 103.51,85.72 E12.3 104.78,87 106.05,88.27 106.05,95.89 | E12.5 103.51,92.08 103.51,93.34 E12.6 104.78,94.61 106.05,95.89 | 106.05,95.89 106.05,125.73 102.87,125.73 97.16,120.02 E16.10
  Bottom 0.254: E9.3 44.45,86.36 50.8,92.71 59.06,92.71 60.33,93.98 62.23,93.98 E10.6 64.77,93.98 66.04,95.25 99.06,95.25 100.33,93.98 102.87,93.98 E12.6
PB0  (via drill 0.61)
  Top 0.254: U$7.K1 17.15,29.21 13.97,29.21 U$2.AK1 | v99.7,19.05 99.06,18.41 99.06,6.99 95.89,3.81 21.59,3.81 v21.59,6.35 | v23.5,7.62 24.13,8.26 24.13,15.24 22.23,17.14 22.23,28.57 v22.86,29.21
  Bottom 0.254: v99.7,19.05 95.25,19.05 94.62,18.41 85.73,18.41 85.09,17.78 E3.4 | v21.59,6.35 22.86,7.62 v23.5,7.62 | v22.86,29.21 18.42,29.21 U$7.K1
PB1  (via drill 0.61)
  Top 0.254: v85.73,7.62 85.73,10.79 84.46,12.06 E3.2 | v40.01,7.62 39.37,8.26 v39.37,52.7 | v31.12,52.07 29.21,50.16 29.21,44.45 28.58,43.81 v28.58,38.1 | v19.05,34.29 17.78,33.02 17.78,32.38 U$7.L1 17.15,31.75 13.97,31.75 U$2.AL1
  Bottom 0.254: v85.73,7.62 83.19,5.08 42.55,5.08 v40.01,7.62 | v39.37,52.7 38.74,52.07 v31.12,52.07 | v28.58,38.1 29.21,38.1 30.48,36.83 30.48,35.56 29.21,35.56 27.94,34.29 26.67,34.29 26.04,34.92 19.69,34.92 v19.05,34.29
PB2  (via drill 0.61)
  Top 0.254: U$7.M1 17.15,35.56 13.97,35.56 U$2.AM1 | v45.72,45.72 45.09,45.09 45.09,8.89 42.55,6.35 27.94,6.35 v27.94,35.56
  Bottom 0.254: v45.72,45.72 54.61,45.72 E6.10 | v27.94,35.56 18.42,35.56 U$7.M1
PB3  (via drill 0.61)
  Top 0.254: U$7.N1 17.15,38.1 13.97,38.1 U$2.AN1 | v22.86,49.53 22.23,48.9 22.23,38.73 v22.86,38.1
  Bottom 0.254: v22.86,49.53 53.34,49.53 54.61,50.8 E6.8 | v22.86,38.1 18.42,38.1 U$7.N1
PB4  (via drill 0.61)
  Top 0.254: v22.86,30.48 v24.77,28.57
  Bottom 0.254: v24.77,28.57 26.04,28.57 26.67,27.94 33.66,27.94 34.29,28.57 59.06,28.57 61.6,31.11 69.22,31.11 69.85,30.48 79.38,30.48 79.38,26.67 78.11,25.4 77.47,25.4 E3.8 | v22.86,30.48 20.96,30.48 U$7.K2 19.69,30.48 13.97,30.48 U$2.AK2
PB5  (via drill 0.61)
  Top 0.254: v60.33,19.05 59.06,20.32 v59.06,29.84 | v22.86,33.02 v26.04,29.84
  Bottom 0.254: v60.33,19.05 73.66,19.05 74.93,20.32 E3.10 | v59.06,29.84 58.42,29.21 33.66,29.21 33.02,28.57 27.31,28.57 v26.04,29.84 | v22.86,33.02 20.96,33.02 U$7.L2 19.69,33.02 13.97,33.02 U$2.AL2
PB6  (via drill 0.61)
  Top 0.254: v80.65,30.48 80.65,19.68 76.84,15.88 E3.12 | v30.48,30.48 28.58,32.38 28.58,34.92 29.21,35.56 v29.21,36.83
  Bottom 0.254: v80.65,30.48 79.38,31.75 48.9,31.75 46.99,29.84 33.02,29.84 32.39,29.21 31.75,29.21 v30.48,30.48 | v29.21,36.83 20.96,36.83 U$7.M2 19.69,36.83 13.97,36.83 U$2.AM2
PB7  (via drill 0.61)
  Top 0.254: v48.9,21.59 46.36,24.13 v46.36,31.75 | v34.93,32.38 31.12,36.2 v31.12,38.73
  Bottom 0.254: v48.9,21.59 81.28,21.59 82.55,22.86 E3.6 | v46.36,31.75 45.72,32.38 v34.93,32.38 | v31.12,38.73 30.48,39.37 20.96,39.37 U$7.N2 19.69,39.37 13.97,39.37 U$2.AN2
PUN_ACTIVE\  (via drill 0.61)
  Top 0.254: 40.64,123.19 40.64,96.52 42.55,94.61 E9.6 | 40.64,123.19 v40.64,126.36 | v26.67,61.59 26.67,115.57 34.29,123.19 40.64,123.19
  Bottom 0.254: E9.11 36.83,88.9 41.91,93.98 E9.6 | v40.64,126.36 56.52,126.36 62.87,120.02 E14.5 | v26.67,61.59 20.96,55.88 U$7.U2 19.69,55.88 13.97,55.88 U$2.AU2
PUN_DONE
  Bottom 0.254: E12.1 103.51,81.92 102.24,83.19 102.24,88.9 102.87,88.9 E12.4 104.78,89.53 106.05,90.81 106.05,95.25 100.33,95.25 96.52,99.06 55.25,99.06 51.44,102.87 50.17,102.87 R14.1 48.9,102.87 43.82,97.79 24.77,97.79 20.96,93.98 U$5.H2 19.69,93.98 13.97,93.98 U$2.BH2
PUN_FLAG  (via drill 0.61)
  Top 0.254: E12.11 95.89,89.53 94.62,90.81 94.62,92.08 95.89,93.34 E12.9 95.89,94.61 95.89,95.89 E12.8 95.89,97.16 95.89,100.97 v91.44,105.41 | v39.37,105.41 39.37,97.79 36.2,94.61 E9.9
  Bottom 0.254: v39.37,105.41 v91.44,105.41
SCR_ACTIVE\  (via drill 0.61)
  Top 0.254: U$5.K1 17.15,99.06 13.97,99.06 U$2.BK1 | v22.86,100.97 22.86,113.03 34.29,124.46 E13.8
  Bottom 0.254: v22.86,100.97 20.96,99.06 18.42,99.06 U$5.K1
SYNC_BIAS  (via drill 0.61)
  Top 0.254: U$2.BU1 13.97,124.46 17.15,124.46 U$5.U1 18.42,124.46 19.69,124.46 21.59,122.56 21.59,74.3 v25.4,70.48
  Bottom 0.254: v25.4,70.48 50.8,70.48 52.71,68.58 R3.1
SYNC_PUN
  Bottom 0.254: R4.1 29.85,66.04 22.23,58.42 20.96,58.42 U$7.V2 19.69,58.42 13.97,58.42 U$2.AV2
SYNC_PUN0  (via drill 0.61)
  Top 0.254: Q2.1 50.17,66.04 48.26,67.94 R7.2 48.26,69.22 52.71,73.66 52.71,116.2 54.61,118.11 57.79,118.11 v57.79,127 | U$5.V1 17.15,127 13.97,127 U$2.BV1
  Bottom 0.254: 57.79,127.64 21.59,127.64 20.96,127 18.42,127 U$5.V1 | 57.79,127.64 98.43,127.64 98.43,118.75 97.16,117.47 E16.11 | v57.79,127 57.79,127.64
VCC
  Top 0.254: E1.14 36.2,9.53 36.83,8.89 36.83,8.26 C1.1 | C9.1 36.83,79.38 36.2,80.01 36.2,80.64 E9.14 35.56,80.64 35.56,55.24 36.83,53.98 C5.1 37.47,53.34 37.47,37.47 36.2,36.2 E5.14 36.2,34.92 36.2,31.75 29.21,24.77 29.21,14.61 30.48,13.34 R5.2 | E15.14 76.84,108.58 77.47,107.95 77.47,107.31 C15.1 | E16.14 97.16,108.58 97.79,107.95 97.79,107.31 C16.1 | E13.14 36.2,108.58 36.83,107.95 36.83,107.31 C13.1 | E14.14 56.52,108.58 57.15,107.95 57.15,107.31 C14.1 57.15,106.05 57.15,103.5 R14.2 57.15,102.23 57.15,100.97 R13.2 57.15,99.69 57.79,99.06 57.79,78.74 C10.1 | C8.1 97.79,53.98 97.79,78.11 C12.1 97.79,79.38 97.79,80.01 97.16,80.64 E12.14 | E3.14 76.84,9.53 77.47,8.89 77.47,8.26 C3.1 | E4.14 97.16,9.53 97.79,8.89 97.79,8.26 C4.1 | C7.1 77.47,53.98 77.47,78.11 C11.1 77.47,79.38 77.47,80.01 76.84,80.64 E11.14 | C10.1 57.15,79.38 56.52,80.01 56.52,80.64 E10.14 | C10.1 57.15,78.11 57.15,71.75 60.33,68.58 R3.2 60.96,67.94 60.96,66.67 R2.2 60.96,65.41 60.96,64.14 R1.2 60.96,62.87 57.15,59.05 57.15,53.98 C6.1 57.79,53.34 57.79,37.47 | C2.1 57.15,8.26 57.15,8.89 56.52,9.53 E2.14 56.52,10.79 57.79,12.06 57.79,37.47 | 57.79,37.47 56.52,36.2 E6.14
  Bottom 0.254: R5.2 31.12,12.7 33.66,10.16 34.29,10.16 E1.14 | C1.1 36.2,7.62 33.66,5.08 23.5,5.08 C17.1 22.23,5.08 20.96,5.08 U$7.A2 19.69,5.08 13.97,5.08 U$2.AA2 | R11.2 25.4,56.52 25.4,59.05 31.75,65.41 31.75,67.31 27.31,67.31 20.32,74.3 U$5.A2 | E9.14 34.29,81.28 29.85,76.83 22.86,76.83 20.96,74.93 U$5.A2 | U$5.A2 19.69,74.93 13.97,74.93 U$2.BA2 | 99.06,110.49 109.86,110.49 111.13,109.22 C20.1 | 99.06,110.49 97.79,109.22 E16.14 | 99.06,110.49 78.74,110.49 77.47,109.22 E15.14 75.57,109.86 74.93,110.49 62.23,110.49 58.42,106.68 57.79,106.68 C14.1 | R10.2 67.95,101.6 66.68,101.6 R9.2 65.41,101.6 64.14,102.87 57.79,102.87 R14.2 | E14.14 54.61,109.22 53.98,109.22 51.44,111.76 R8.2 50.17,111.76 46.36,107.95 41.91,107.95 41.28,108.58 37.47,108.58 36.83,109.22 E13.14 | C21.1 111.13,81.28 109.86,80.01 99.7,80.01 98.43,78.74 C12.1 | C18.1 111.13,10.16 107.32,6.35 99.7,6.35 98.43,7.62 C4.1 | C3.1 78.11,7.62 79.38,8.89 93.98,8.89 95.25,10.16 E4.14 | 73.66,36.83 74.93,35.56 E7.14 | 73.66,36.83 58.42,36.83 57.15,35.56 E6.14 | 93.98,36.83 95.25,35.56 E8.14 | 73.66,36.83 93.98,36.83 | 93.98,36.83 109.86,36.83 111.13,35.56 C19.1 | 73.66,82.55 74.93,81.28 E11.14 | 73.66,82.55 58.42,82.55 57.15,81.28 E10.14 | E3.14 74.93,10.16 73.66,8.89 61.6,8.89 60.33,10.16 57.15,10.16 E2.14 | 73.66,82.55 93.98,82.55 95.25,81.28 E12.14 | C5.1 37.47,53.34 38.74,54.61 55.25,54.61 56.52,53.34 C6.1

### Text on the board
Top: M710
Bottom: M710
tNames: V1 | V1 | V1 | V1 | V1 | V1 | V1 | V1 | V1 | V1 | V1 | V1 | V1 | V1 | V1 | V1 | V1 | V1 | V1 | V1 | V1 | V1 | V1 | V1 | V1 | V1 | V1 | V1 | V1 | V1 | V1 | V1 | A1 | A1 | A1 | A1 | A1 | A1 | A1 | A1 | A1 | A1 | A1 | A1 | A1 | A1 | A1 | A1 | A1 | A1 | A1 | A1 | A1 | A1 | A1 | A1 | A1 | A1 | A1 | A1 | A1 | A1 | A1 | A1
